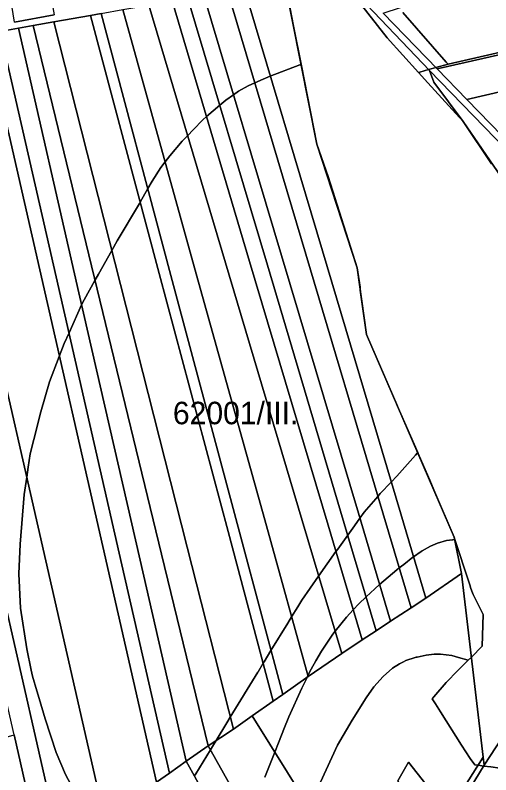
# Model space of a CAD drawing. Extents: x -521939 to -516426, y -1197857 to -1189551.
# Drawn here: x -519682 to -519365, y -1193908 to -1193402 of the extents above; entities that cross this region are included whole.
import ezdxf

# ---------------------------------------------------------------- set-up
doc = ezdxf.new("R2010")
doc.units = 0
for name, color, linetype in [('95560013', 7, 'Continuous'), ('95610013', 7, 'Continuous'), ('95620013', 7, 'Continuous'), ('95630013', 7, 'Continuous'), ('95640013', 7, 'Continuous'), ('95660013', 7, 'Continuous')]:
    doc.layers.add(name, color=color, linetype=linetype)

msp = doc.modelspace()

# ---------------------------------------------------------------- linework, layer by layer
at = {"layer": '95560013'}
for points in [[(-519655.8, -1193401.93), (-519682.31, -1193406.66), (-519694.28, -1193333.23), (-519723.2, -1193155.82), (-519701.27, -1193154.26), (-519668.98, -1193330.14)], [(-519529.4, -1193383.96), (-519477.18, -1193559.19), (-519424.96, -1193734.42), (-519408.2, -1193790.66), (-519418.05, -1193797.11), (-519436.86, -1193733.88), (-519488.2, -1193561.3), (-519540.37, -1193385.93)], [(-519502.33, -1193379.15), (-519480.86, -1193488.16), (-519453.95, -1193570.4), (-519447.84, -1193614.85), (-519389.47, -1193750.04), (-519384.42, -1193774.3), (-519408.2, -1193790.66), (-519424.96, -1193734.42), (-519477.18, -1193559.19), (-519529.4, -1193383.96)], [(-519556.16, -1193388.74), (-519504.45, -1193562.19), (-519453.22, -1193734.03), (-519431.74, -1193806.08), (-519441.36, -1193812.44), (-519460.82, -1193746.98), (-519513.84, -1193568.63), (-519566.75, -1193390.65)], [(-519540.37, -1193385.93), (-519488.2, -1193561.3), (-519436.86, -1193733.88), (-519418.05, -1193797.11), (-519431.74, -1193806.08), (-519453.22, -1193734.03), (-519504.45, -1193562.19), (-519556.16, -1193388.74)], [(-519577.25, -1193392.51), (-519525.65, -1193566.15), (-519473.42, -1193741.91), (-519450.66, -1193818.5), (-519464.32, -1193827.57), (-519490.71, -1193738.79), (-519541.76, -1193567.05), (-519592.81, -1193395.31)], [(-519441.36, -1193812.44), (-519450.66, -1193818.5), (-519473.42, -1193741.91), (-519525.65, -1193566.15), (-519577.25, -1193392.51), (-519566.75, -1193390.65), (-519513.84, -1193568.63), (-519460.82, -1193746.98)], [(-519610.06, -1193398.36), (-519562.28, -1193570.44), (-519514.5, -1193742.52), (-519486.62, -1193842.93), (-519503.63, -1193854.82), (-519531.55, -1193750.06), (-519578.07, -1193575.51), (-519624.59, -1193400.96)], [(-519464.32, -1193827.57), (-519486.62, -1193842.93), (-519514.5, -1193742.52), (-519562.28, -1193570.44), (-519610.06, -1193398.36), (-519592.81, -1193395.31), (-519541.76, -1193567.05), (-519490.71, -1193738.79)], [(-519656.13, -1193406.57), (-519631.73, -1193402.24), (-519585.9, -1193574.19), (-519540.03, -1193746.29), (-519509.92, -1193859.26), (-519524.03, -1193869.16), (-519536.51, -1193877.89), (-519567.25, -1193756.77), (-519611.69, -1193581.67)], [(-519631.73, -1193402.24), (-519624.59, -1193400.96), (-519578.07, -1193575.51), (-519531.55, -1193750.06), (-519503.63, -1193854.82), (-519509.92, -1193859.26), (-519540.03, -1193746.29), (-519585.9, -1193574.19)], [(-519553.25, -1193889.05), (-519568.04, -1193899.4), (-519598.68, -1193765.35), (-519639.39, -1193587.24), (-519679.73, -1193410.75), (-519669.99, -1193409.03), (-519627.26, -1193584.73), (-519584.29, -1193761.42)], [(-519669.99, -1193409.03), (-519656.13, -1193406.57), (-519611.69, -1193581.67), (-519567.25, -1193756.77), (-519536.51, -1193877.89), (-519553.25, -1193889.05), (-519584.29, -1193761.42), (-519627.26, -1193584.73)], [(-519701.52, -1193414.64), (-519691.78, -1193412.9), (-519651.6, -1193589.16), (-519612.48, -1193760.77), (-519579.1, -1193907.2), (-519587.75, -1193913.3)], [(-519679.73, -1193410.75), (-519639.39, -1193587.24), (-519598.68, -1193765.35), (-519568.04, -1193899.4), (-519579.1, -1193907.2), (-519612.48, -1193760.77), (-519651.6, -1193589.16), (-519691.78, -1193412.9)], [(-519739.99, -1193421.5), (-519725.47, -1193418.95), (-519701.52, -1193414.64), (-519587.75, -1193913.3), (-519609.4, -1193928.24), (-519622.78, -1193935.57)], [(-519652.7, -1193951.75), (-519692.33, -1193778.37), (-519736.87, -1193583.51), (-519772.58, -1193427.28), (-519739.99, -1193421.5), (-519622.78, -1193935.57), (-519633.36, -1193941.29)], [(-519652.7, -1193951.75), (-519657.74, -1193954.5), (-519665.13, -1193958.51), (-519682.62, -1193881.84), (-519704.7, -1193785.08), (-519745.25, -1193607.38), (-519785.8, -1193429.68), (-519772.58, -1193427.28), (-519736.87, -1193583.51), (-519692.33, -1193778.37)], [(-519665.13, -1193958.51), (-519687.29, -1193970.52), (-519709.36, -1193889.56), (-519682.62, -1193881.84)]]:
    msp.add_lwpolyline(points, close=True, dxfattribs=at)
at = {"layer": '95610013'}
for points in [[(-519216.77, -1193386.17), (-519201.14, -1193416.51), (-519380.85, -1193458.26), (-519400.65, -1193437.87), (-519323.14, -1193420.3), (-519244.63, -1193400.06), (-519224.13, -1193393.57)], [(-519186.96, -1193442.78), (-519357.29, -1193482.57), (-519380.85, -1193458.26), (-519201.14, -1193416.51)], [(-519405.79, -1193439.04), (-519317.99, -1193529.4), (-519300.03, -1193548.89), (-519283.14, -1193569.31), (-519275.11, -1193579.85), (-519265.95, -1193592.56), (-519264.31, -1193598.43), (-519252.73, -1193614.95), (-519278.45, -1193629.39), (-519292.71, -1193607.08), (-519298.97, -1193590.8), (-519316.99, -1193567.29), (-519355.68, -1193513.49), (-519383.3, -1193472.91), (-519402.88, -1193446.79)], [(-519524.03, -1193869.16), (-519488.68, -1193925.71), (-519511.04, -1193938.78), (-519477.05, -1193998.98), (-519450.62, -1194041.02), (-519444.35, -1194050.85), (-519439.91, -1194057.85), (-519441.81, -1194062.27), (-519444.29, -1194066.37), (-519447.56, -1194070.22), (-519450.52, -1194072.35), (-519465.54, -1194045.55), (-519553.25, -1193889.05), (-519536.51, -1193877.89)], [(-519553.25, -1193889.05), (-519465.54, -1194045.55), (-519450.52, -1194072.35), (-519456, -1194075.37), (-519468.13, -1194079.41), (-519475.09, -1194066.87), (-519568.04, -1193899.4)], [(-519468.13, -1194079.41), (-519520.93, -1194095.96), (-519609.4, -1193928.24), (-519587.75, -1193913.3), (-519579.1, -1193907.2), (-519568.04, -1193899.4), (-519475.09, -1194066.87)], [(-519426.85, -1193912.47), (-519419.72, -1193900.08), (-519393.46, -1193933.48), (-519401.16, -1193945.56)]]:
    msp.add_lwpolyline(points, close=True, dxfattribs=at)
at = {"layer": '95620013'}
msp.add_lwpolyline([(-519049.8, -1193274.26), (-519040.03, -1193304.65), (-519061.29, -1193334.23), (-519127.73, -1193353.98), (-519195.16, -1193370.61), (-519207.67, -1193377.01), (-519216.77, -1193386.17), (-519224.13, -1193393.57), (-519244.63, -1193400.06), (-519323.14, -1193420.3), (-519400.65, -1193437.87), (-519436.58, -1193400.77), (-519414.21, -1193393.4), (-519363, -1193379.33), (-519272.27, -1193354.6), (-519242.56, -1193344.82), (-519244.89, -1193329.7), (-519245.64, -1193323.44), (-519072.06, -1193279.85)], close=True, dxfattribs=at)
for points in [[(-519323.09, -1193831.25), (-519369.32, -1193902.04), (-519369.96, -1193896.6), (-519384.42, -1193774.3), (-519389.47, -1193750.04), (-519447.84, -1193614.85), (-519453.95, -1193570.4), (-519480.86, -1193488.16), (-519502.33, -1193379.15)], [(-519452.18, -1193390.07), (-519405.79, -1193439.04), (-519402.88, -1193446.79), (-519383.3, -1193472.91), (-519355.68, -1193513.49)]]:
    msp.add_lwpolyline(points, dxfattribs=at)
at = {"layer": '95630013'}
msp.add_lwpolyline([(-519392.44, -1193939.94), (-519369.32, -1193902.04), (-519323.09, -1193831.25)], dxfattribs=at)
at = {"layer": '95640013'}
for points in [[(-519317.99, -1193529.4), (-519405.79, -1193439.04), (-519452.18, -1193390.07)], [(-519624.59, -1193400.96), (-519631.73, -1193402.24), (-519656.13, -1193406.57), (-519669.99, -1193409.03), (-519679.73, -1193410.75), (-519691.78, -1193412.9)], [(-519682.31, -1193406.66), (-519655.8, -1193401.93)], [(-519436.58, -1193400.77), (-519400.65, -1193437.87), (-519380.85, -1193458.26), (-519357.29, -1193482.57)], [(-519488.68, -1193925.71), (-519524.03, -1193869.16), (-519509.92, -1193859.26), (-519503.63, -1193854.82), (-519486.62, -1193842.93), (-519464.32, -1193827.57), (-519450.66, -1193818.5), (-519441.36, -1193812.44), (-519431.74, -1193806.08), (-519418.05, -1193797.11), (-519408.2, -1193790.66), (-519384.42, -1193774.3), (-519369.96, -1193896.6), (-519393.46, -1193933.48), (-519419.72, -1193900.08), (-519426.85, -1193912.47)]]:
    msp.add_lwpolyline(points, dxfattribs=at)
msp.add_lwpolyline([(-519393.46, -1193933.48), (-519369.96, -1193896.6), (-519369.32, -1193902.04), (-519392.44, -1193939.94), (-519401.67, -1193955.07), (-519417.38, -1193986.45), (-519423.71, -1194026.84), (-519422.25, -1194029.85), (-519423.14, -1194034.81), (-519428.59, -1194030.27), (-519428.22, -1194027.94), (-519425.91, -1194013.45), (-519422.59, -1193993.31), (-519420.77, -1193981.9), (-519415.68, -1193971.51), (-519408.84, -1193958.58), (-519404.57, -1193950.95), (-519401.16, -1193945.56)], close=True, dxfattribs=at)
at = {"layer": '95660013'}
for points in [[(-519499.78, -1193392.08), (-519496.37, -1193409.42), (-519491.37, -1193434.82), (-519492.01, -1193435.07), (-519492.24, -1193435.16), (-519511.88, -1193442.76), (-519516.71, -1193444.63), (-519522.16, -1193447.13), (-519526.57, -1193449.15), (-519533.06, -1193452.74), (-519536.39, -1193455.06), (-519541.52, -1193458.65), (-519545.51, -1193462.1), (-519554.31, -1193469.7), (-519556.82, -1193471.87), (-519563.18, -1193478.44), (-519566.94, -1193482.33), (-519570.61, -1193486.12), (-519578.84, -1193495.86), (-519581.91, -1193499.75), (-519584.87, -1193503.51), (-519590.67, -1193512.67), (-519593.48, -1193517.7), (-519598.54, -1193526.77), (-519599.01, -1193527.62), (-519613.85, -1193552.42), (-519617.47, -1193558.89), (-519626.37, -1193574.79), (-519628.69, -1193578.87), (-519635.99, -1193591.72), (-519637.57, -1193595.21), (-519645.98, -1193613.81), (-519649.2, -1193620.93), (-519652.5, -1193629.48), (-519659.05, -1193646.43), (-519664.67, -1193666.42), (-519665.89, -1193670.77), (-519667.04, -1193675.35), (-519671.8, -1193694.41), (-519673.16, -1193703.3), (-519674.2, -1193710.06), (-519675.98, -1193721.65), (-519678.64, -1193754.69), (-519679.45, -1193774.51), (-519678.29, -1193797.23), (-519674.12, -1193824.35), (-519671.21, -1193838.7), (-519670.41, -1193842.67), (-519667.48, -1193852.49), (-519665.99, -1193857.5), (-519661.95, -1193871.06), (-519654.65, -1193893.55), (-519648.39, -1193908.27), (-519641.43, -1193921.14)], [(-519323.09, -1193831.25), (-519365.52, -1193896.23), (-519369.32, -1193902.04), (-519369.63, -1193902.55), (-519373.43, -1193902.05), (-519375.53, -1193901.78), (-519378.72, -1193897.58), (-519384.43, -1193888.71), (-519398.41, -1193866.52), (-519401.86, -1193861.03), (-519403.96, -1193857.7), (-519402.93, -1193856.48), (-519394.8, -1193846.87), (-519386.91, -1193838.98), (-519380, -1193832.07), (-519377.84, -1193829.93), (-519370.61, -1193822.74), (-519370.09, -1193801.62), (-519373.12, -1193795.42), (-519376.18, -1193789.15), (-519376.69, -1193788.12), (-519377.19, -1193787.1), (-519378.17, -1193784.15), (-519378.98, -1193781.74), (-519379.64, -1193779.74), (-519388.98, -1193751.54), (-519389.47, -1193750.04), (-519402.85, -1193718.4), (-519405.55, -1193712.01), (-519413.29, -1193694.33), (-519413.6, -1193693.61), (-519427.35, -1193662.21), (-519427.67, -1193661.56), (-519447.84, -1193614.85), (-519451.9, -1193585.3), (-519452.02, -1193583.47), (-519453.95, -1193570.4), (-519473.33, -1193509.63), (-519480.86, -1193488.16), (-519491.37, -1193434.82), (-519496.37, -1193409.42), (-519499.78, -1193392.08)], [(-519453.32, -1193392.59), (-519433.92, -1193417.09), (-519413.1, -1193440.27), (-519406.93, -1193447.14), (-519392.87, -1193462.47), (-519383.3, -1193472.91), (-519364.55, -1193501.1)], [(-519423.63, -1193400.22), (-519394.68, -1193433.31), (-519394.03, -1193434.06), (-519393.46, -1193434.71), (-519401.51, -1193436.99), (-519404.63, -1193437.87), (-519406.41, -1193438.38), (-519412.31, -1193440.05), (-519413.1, -1193440.27), (-519433.92, -1193417.09), (-519453.32, -1193392.59)], [(-519246.07, -1193397.49), (-519324.52, -1193418.94), (-519393.46, -1193434.71), (-519394.03, -1193434.06), (-519394.68, -1193433.31), (-519423.63, -1193400.22)], [(-519364.55, -1193501.1), (-519383.3, -1193472.91), (-519392.87, -1193462.47), (-519406.93, -1193447.14), (-519413.1, -1193440.27), (-519412.31, -1193440.05), (-519406.41, -1193438.38), (-519404.63, -1193437.87), (-519401.51, -1193436.99), (-519393.46, -1193434.71), (-519324.52, -1193418.94)], [(-519641.43, -1193921.14), (-519648.39, -1193908.27), (-519654.65, -1193893.55), (-519661.95, -1193871.06), (-519665.99, -1193857.5), (-519667.48, -1193852.49), (-519670.41, -1193842.67), (-519671.21, -1193838.7), (-519674.12, -1193824.35), (-519678.29, -1193797.23), (-519679.45, -1193774.51), (-519678.64, -1193754.69), (-519675.98, -1193721.65), (-519674.2, -1193710.06), (-519673.16, -1193703.3), (-519671.8, -1193694.41), (-519667.04, -1193675.35), (-519665.89, -1193670.77), (-519664.67, -1193666.42), (-519659.05, -1193646.43), (-519652.5, -1193629.48), (-519649.2, -1193620.93), (-519645.98, -1193613.81), (-519637.57, -1193595.21), (-519635.99, -1193591.72), (-519628.69, -1193578.87), (-519626.37, -1193574.79), (-519617.47, -1193558.89), (-519613.85, -1193552.42), (-519599.01, -1193527.62), (-519598.54, -1193526.77), (-519593.48, -1193517.7), (-519590.67, -1193512.67), (-519584.87, -1193503.51), (-519581.91, -1193499.75), (-519578.84, -1193495.86), (-519570.61, -1193486.12), (-519566.94, -1193482.33), (-519563.18, -1193478.44), (-519556.82, -1193471.87), (-519554.31, -1193469.7), (-519545.51, -1193462.1), (-519541.52, -1193458.65), (-519536.39, -1193455.06), (-519533.06, -1193452.74), (-519526.57, -1193449.15), (-519522.16, -1193447.13), (-519516.71, -1193444.63), (-519511.88, -1193442.76), (-519492.24, -1193435.16), (-519492.01, -1193435.07), (-519491.37, -1193434.82), (-519480.86, -1193488.16), (-519473.33, -1193509.63), (-519453.95, -1193570.4), (-519452.02, -1193583.47), (-519451.9, -1193585.3), (-519447.84, -1193614.85), (-519427.67, -1193661.56), (-519427.35, -1193662.21), (-519413.6, -1193693.61), (-519413.67, -1193693.69), (-519413.76, -1193693.78), (-519415.09, -1193695.28), (-519427.58, -1193709.37), (-519431.27, -1193713.25), (-519438.59, -1193720.96), (-519440.16, -1193722.79), (-519441.53, -1193724.38), (-519449.25, -1193733.36), (-519452.2, -1193737.45), (-519455.79, -1193742.42), (-519460.31, -1193748.68), (-519466.99, -1193757.93), (-519468.16, -1193759.6), (-519479.66, -1193775.96), (-519490.87, -1193791.9), (-519493.63, -1193796.42), (-519497.69, -1193803.07), (-519500.27, -1193807.31), (-519511.42, -1193825.58), (-519516.07, -1193833.19), (-519516.63, -1193834.1), (-519520.07, -1193839.74), (-519520.25, -1193840.03), (-519538.52, -1193869.96), (-519540.82, -1193873.73), (-519548.01, -1193885.56), (-519549.78, -1193888.47), (-519551.75, -1193891.72), (-519561.46, -1193907.69), (-519562.51, -1193909.36)], [(-519562.51, -1193909.36), (-519561.46, -1193907.69), (-519551.75, -1193891.72), (-519549.78, -1193888.47), (-519548.01, -1193885.56), (-519540.82, -1193873.73), (-519538.52, -1193869.96), (-519520.25, -1193840.03), (-519520.07, -1193839.74), (-519516.63, -1193834.1), (-519516.07, -1193833.19), (-519511.42, -1193825.58), (-519500.27, -1193807.31), (-519497.69, -1193803.07), (-519493.63, -1193796.42), (-519490.87, -1193791.9), (-519479.66, -1193775.96), (-519468.16, -1193759.6), (-519466.99, -1193757.93), (-519460.31, -1193748.68), (-519455.79, -1193742.42), (-519452.2, -1193737.45), (-519449.25, -1193733.36), (-519441.53, -1193724.38), (-519440.16, -1193722.79), (-519438.59, -1193720.96), (-519431.27, -1193713.25), (-519427.58, -1193709.37), (-519415.09, -1193695.28), (-519413.76, -1193693.78), (-519413.67, -1193693.69), (-519413.6, -1193693.61), (-519413.29, -1193694.33), (-519405.55, -1193712.01), (-519402.85, -1193718.4), (-519389.47, -1193750.04), (-519388.98, -1193751.54), (-519389.15, -1193751.56), (-519390.34, -1193751.69), (-519390.4, -1193751.69), (-519394.54, -1193752.14), (-519400.51, -1193753.94), (-519405.15, -1193756.02), (-519410.71, -1193759.15), (-519411.36, -1193759.59), (-519416.43, -1193763.03), (-519416.86, -1193763.32), (-519422.95, -1193768.16), (-519425.95, -1193770.55), (-519427.52, -1193771.79), (-519439.02, -1193781.66), (-519442.24, -1193784.42), (-519448.07, -1193789.87), (-519452.9, -1193794.39), (-519456.62, -1193798.43), (-519461.13, -1193803.31), (-519461.22, -1193803.42), (-519468.72, -1193812.75), (-519470.18, -1193814.56), (-519477.83, -1193826.03), (-519481.5, -1193832.45), (-519484.66, -1193837.97), (-519486.79, -1193842.32), (-519487.34, -1193843.44), (-519490.92, -1193850.72), (-519499.5, -1193869.73), (-519499.97, -1193870.92), (-519502.33, -1193876.88), (-519506.34, -1193887), (-519508.91, -1193893.35), (-519515.61, -1193909.95)], [(-519515.61, -1193909.95), (-519508.91, -1193893.35), (-519506.34, -1193887), (-519502.33, -1193876.88), (-519499.97, -1193870.92), (-519499.5, -1193869.73), (-519490.92, -1193850.72), (-519487.34, -1193843.44), (-519486.79, -1193842.32), (-519484.66, -1193837.97), (-519481.5, -1193832.45), (-519477.83, -1193826.03), (-519470.18, -1193814.56), (-519468.72, -1193812.75), (-519461.22, -1193803.42), (-519461.13, -1193803.31), (-519456.62, -1193798.43), (-519452.9, -1193794.39), (-519448.07, -1193789.87), (-519442.24, -1193784.42), (-519439.02, -1193781.66), (-519427.52, -1193771.79), (-519425.95, -1193770.55), (-519422.95, -1193768.16), (-519416.86, -1193763.32), (-519416.43, -1193763.03), (-519411.36, -1193759.59), (-519410.71, -1193759.15), (-519405.15, -1193756.02), (-519400.51, -1193753.94), (-519394.54, -1193752.14), (-519390.4, -1193751.69), (-519390.34, -1193751.69), (-519389.15, -1193751.56), (-519388.98, -1193751.54), (-519379.64, -1193779.74), (-519378.98, -1193781.74), (-519378.17, -1193784.15), (-519377.19, -1193787.1), (-519376.69, -1193788.12), (-519376.18, -1193789.15), (-519373.12, -1193795.42), (-519370.09, -1193801.62), (-519370.61, -1193822.74), (-519377.84, -1193829.93), (-519380, -1193832.07), (-519386.56, -1193830.12), (-519390.96, -1193828.96), (-519394.79, -1193828.38), (-519398.38, -1193828.03), (-519402.67, -1193828.03), (-519408, -1193828.61), (-519414.01, -1193829.95), (-519414.63, -1193830.08), (-519415.31, -1193830.23), (-519421.57, -1193832.32), (-519423.17, -1193833.1), (-519425.85, -1193834.41), (-519430.37, -1193837.42), (-519436.75, -1193842.87), (-519442.89, -1193849.82), (-519447.99, -1193857.13), (-519457.38, -1193871.96), (-519467.12, -1193888.54), (-519478.44, -1193913.36)], [(-519478.44, -1193913.36), (-519467.12, -1193888.54), (-519457.38, -1193871.96), (-519447.99, -1193857.13), (-519442.89, -1193849.82), (-519436.75, -1193842.87), (-519430.37, -1193837.42), (-519425.85, -1193834.41), (-519423.17, -1193833.1), (-519421.57, -1193832.32), (-519415.31, -1193830.23), (-519414.63, -1193830.08), (-519414.01, -1193829.95), (-519408, -1193828.61), (-519402.67, -1193828.03), (-519398.38, -1193828.03), (-519394.79, -1193828.38), (-519390.96, -1193828.96), (-519386.56, -1193830.12), (-519380, -1193832.07), (-519386.91, -1193838.98), (-519394.8, -1193846.87), (-519402.93, -1193856.48), (-519403.96, -1193857.7), (-519401.86, -1193861.03), (-519398.41, -1193866.52), (-519384.43, -1193888.71), (-519378.72, -1193897.58), (-519375.53, -1193901.78), (-519373.43, -1193902.05), (-519369.63, -1193902.55), (-519365.04, -1193903.15), (-519358.93, -1193903.95)], [(-519358.93, -1193903.95), (-519365.04, -1193903.15), (-519369.63, -1193902.55), (-519369.32, -1193902.04), (-519365.52, -1193896.23), (-519323.09, -1193831.25)]]:
    msp.add_lwpolyline(points, dxfattribs=at)

# ---------------------------------------------------------------- texts
msp.add_text('62001/III.', height=15, rotation=360, dxfattribs=at).set_placement((-519576.79, -1193674.75))

doc.saveas('drawing.dxf')
